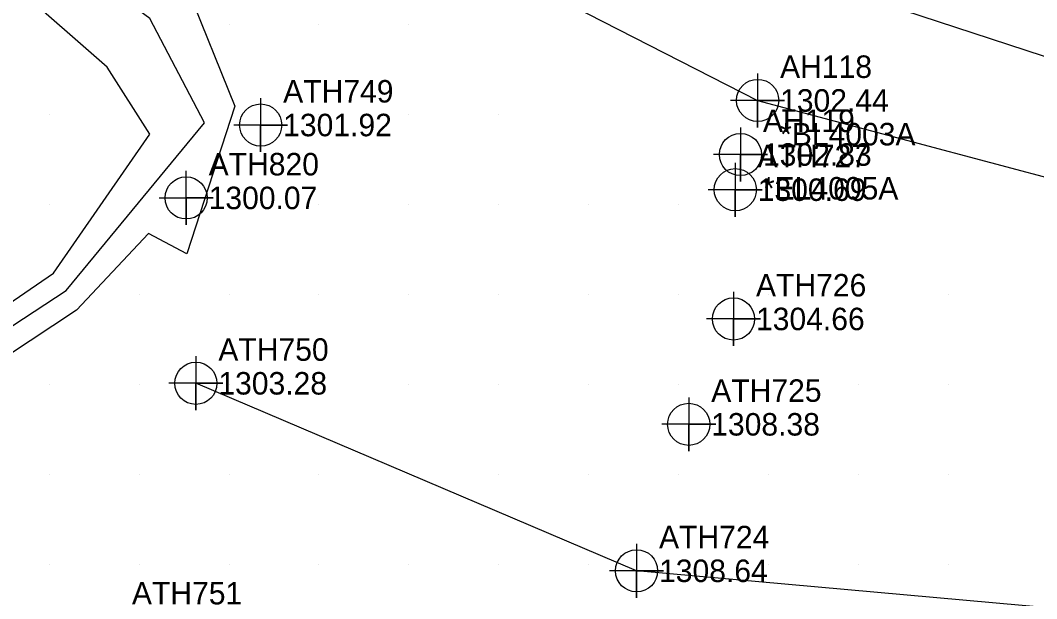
# Model space of a CAD drawing. Extents: x 1234484 to 1235382, y 695050 to 695510.
# Drawn here: x 1234936.8 to 1235049.8, y 695206.2 to 695270.5 of the extents above; entities that cross this region are included whole.
import ezdxf

# ---------------------------------------------------------------- set-up
doc = ezdxf.new("R2010")
doc.units = 0
for name, color, linetype in [('Exist DTM Breakline', 7, 'Continuous'), ('Exist DTM Breakline Cogo Comment', 7, 'Continuous'), ('Exist DTM Breakline Cogo Elevation', 7, 'Continuous'), ('Exist DTM Breakline Cogo Number', 7, 'Continuous'), ('Exist DTM Breakline Cogo Point CELL', 7, 'Continuous'), ('Exist DTM Breakline Underwater', 7, 'Continuous'), ('Exist DTM Crownline', 7, 'Continuous'), ('Exist DTM Drainline Cogo Comment', 7, 'Continuous'), ('Exist DTM Drainline Cogo Elevation', 7, 'Continuous'), ('Exist DTM Drainline Cogo Number', 7, 'Continuous'), ('Exist DTM Drainline Cogo Point CELL', 7, 'Continuous'), ('Exist DTM QL2 LIDAR Elevation Point', 7, 'Continuous'), ('Exist DTM Regular Point CELL', 7, 'Continuous'), ('Exist DTM Regular Point Cogo Elevation', 7, 'Continuous'), ('Exist DTM Regular Point Cogo Number', 7, 'Continuous'), ('Exist DTM Regular Point Underwater CELL', 7, 'Continuous'), ('Exist DTM Regular Point Underwater Cogo Elevation', 7, 'Continuous'), ('Exist DTM Regular Point Underwater Cogo Number', 7, 'Continuous'), ('Exist Hydro Stream or Body of Water', 7, 'Continuous'), ('Exist Hydro Stream or Body of Water Cogo Elevation', 7, 'Continuous'), ('Exist Hydro Stream or Body of Water Cogo Number', 7, 'Continuous'), ('Exist Hydro Stream or Body of Water Cogo Point CELL', 7, 'Continuous'), ('Exist Roads EOP', 7, 'Continuous')]:
    doc.layers.add(name, color=color, linetype=linetype)

msp = doc.modelspace()

# ---------------------------------------------------------------- linework, layer by layer
at = {"layer": 'Exist DTM Breakline'}
for points in [[(1234933.683, 695295.436), (1234929.419, 695292.356), (1234942.895, 695281.98), (1234955.338, 695274.07), (1234960.662, 695260.925), (1234955.311, 695244.507), (1234951.042, 695246.761), (1234943.062, 695238.239), (1234919.786, 695222.886), (1234917.573, 695214.076), (1234899.933, 695199.243), (1234885.657, 695179.089)], [(1234882.128, 695182.331), (1234896.107, 695201.799), (1234912.336, 695216.249), (1234916.953, 695226.235), (1234940.483, 695242.348), (1234951.207, 695257.798), (1234946.446, 695265.278), (1234936.421, 695274.091), (1234919.314, 695287.826), (1234914.388, 695289.733)], [(1235242.403, 695122.486), (1235188.913, 695150.987), (1235163.662, 695164.651), (1235112.238, 695183.191), (1235055.183, 695204.784), (1235005.3, 695209.27), (1234956.312, 695230.116)]]:
    msp.add_lwpolyline(points, dxfattribs=at)
at = {"layer": 'Exist DTM Breakline Cogo Point CELL'}
for points in [[(1235016.848, 695258.551), (1235016.848, 695252.551), (1235016.848, 695255.551), (1235019.848, 695255.551), (1235013.848, 695255.551)], [(1234956.312, 695233.116), (1234956.312, 695227.116), (1234956.312, 695230.116), (1234959.312, 695230.116), (1234953.312, 695230.116)], [(1235005.3, 695212.27), (1235005.3, 695206.27), (1235005.3, 695209.27), (1235008.3, 695209.27), (1235002.3, 695209.27)]]:
    msp.add_lwpolyline(points, dxfattribs=at)
for centre in [(1235016.848, 695255.551), (1234956.312, 695230.116), (1235005.3, 695209.27)]:
    msp.add_circle(centre, 2.344, dxfattribs=at)
at = {"layer": 'Exist DTM Breakline Underwater'}
msp.add_lwpolyline([(1234948.239, 695292.841), (1234952.805, 695292.84), (1234960.83, 695292.864), (1234972.599, 695288.481), (1235023.203, 695275.502), (1235056.399, 695264.585), (1235086.587, 695258.395), (1235121.582, 695234.941), (1235168.445, 695213.485), (1235191.313, 695204.186), (1235209.05, 695188.429), (1235246.922, 695166.749), (1235265.478, 695149.496)], dxfattribs=at)
at = {"layer": 'Exist DTM Crownline'}
msp.add_spline([(1234978.534, 695313.159), (1235028.867, 695302.317), (1235079.475, 695286.154), (1235130.202, 695265.942), (1235178.94, 695242.599), (1235226.8, 695217.474)], degree=3, dxfattribs=at)
at = {"layer": 'Exist DTM Drainline Cogo Point CELL'}
msp.add_lwpolyline([(1235018.754, 695264.568), (1235018.754, 695258.568), (1235018.754, 695261.568), (1235021.754, 695261.568), (1235015.754, 695261.568)], dxfattribs=at)
msp.add_circle((1235018.754, 695261.568), 2.344, dxfattribs=at)
at = {"layer": 'Exist DTM QL2 LIDAR Elevation Point'}
for p, q in [((1234960, 695270), (1234960, 695270)), ((1234970, 695270), (1234970, 695270)), ((1234980, 695270), (1234980, 695270)), ((1234940, 695260), (1234940, 695260)), ((1234970, 695260), (1234970, 695260)), ((1234980, 695260), (1234980, 695260)), ((1234990, 695260), (1234990, 695260)), ((1234940, 695250), (1234940, 695250)), ((1234960, 695250), (1234960, 695250)), ((1234970, 695250), (1234970, 695250)), ((1234980, 695250), (1234980, 695250)), ((1234990, 695250), (1234990, 695250)), ((1235000, 695250), (1235000, 695250)), ((1235010, 695250), (1235010, 695250)), ((1234950, 695240), (1234950, 695240)), ((1234960, 695240), (1234960, 695240)), ((1234970, 695240), (1234970, 695240)), ((1234980, 695240), (1234980, 695240)), ((1234990, 695240), (1234990, 695240)), ((1235000, 695240), (1235000, 695240)), ((1235010, 695240), (1235010, 695240)), ((1235020, 695240), (1235020, 695240)), ((1235030, 695240), (1235030, 695240)), ((1235040, 695240), (1235040, 695240)), ((1234940, 695230), (1234940, 695230)), ((1234950, 695230), (1234950, 695230)), ((1234960, 695230), (1234960, 695230)), ((1234970, 695230), (1234970, 695230)), ((1234980, 695230), (1234980, 695230)), ((1234990, 695230), (1234990, 695230)), ((1235000, 695230), (1235000, 695230)), ((1235010, 695230), (1235010, 695230)), ((1235020, 695230), (1235020, 695230)), ((1235030, 695230), (1235030, 695230)), ((1235040, 695230), (1235040, 695230)), ((1234940, 695220), (1234940, 695220)), ((1234950, 695220), (1234950, 695220)), ((1234960, 695220), (1234960, 695220)), ((1234970, 695220), (1234970, 695220)), ((1234990, 695220), (1234990, 695220)), ((1235000, 695220), (1235000, 695220)), ((1235010, 695220), (1235010, 695220)), ((1235020, 695220), (1235020, 695220)), ((1235030, 695220), (1235030, 695220)), ((1235040, 695220), (1235040, 695220)), ((1234940, 695210), (1234940, 695210)), ((1234950, 695210), (1234950, 695210)), ((1234960, 695210), (1234960, 695210)), ((1234970, 695210), (1234970, 695210)), ((1234980, 695210), (1234980, 695210)), ((1234990, 695210), (1234990, 695210)), ((1235000, 695210), (1235000, 695210)), ((1235010, 695210), (1235010, 695210)), ((1235020, 695210), (1235020, 695210)), ((1235030, 695210), (1235030, 695210)), ((1235040, 695210), (1235040, 695210))]:
    msp.add_line(p, q, dxfattribs=at)
at = {"layer": 'Exist DTM Regular Point CELL'}
for points in [[(1234963.516, 695261.834), (1234963.516, 695255.834), (1234963.516, 695258.834), (1234966.516, 695258.834), (1234960.516, 695258.834)], [(1235016.075, 695240.272), (1235016.075, 695234.272), (1235016.075, 695237.272), (1235019.075, 695237.272), (1235013.075, 695237.272)], [(1235011.1, 695228.556), (1235011.1, 695222.556), (1235011.1, 695225.556), (1235014.1, 695225.556), (1235008.1, 695225.556)]]:
    msp.add_lwpolyline(points, dxfattribs=at)
for centre in [(1234963.516, 695258.834), (1235016.075, 695237.272), (1235011.1, 695225.556)]:
    msp.add_circle(centre, 2.344, dxfattribs=at)
at = {"layer": 'Exist DTM Regular Point Underwater CELL'}
msp.add_lwpolyline([(1235016.271, 695254.643), (1235016.271, 695248.643), (1235016.271, 695251.643), (1235019.271, 695251.643), (1235013.271, 695251.643)], dxfattribs=at)
msp.add_circle((1235016.271, 695251.643), 2.344, dxfattribs=at)
at = {"layer": 'Exist Hydro Stream or Body of Water'}
for points in [[(1234884.024, 695180.655), (1234897.944, 695200.742), (1234915.887, 695215.628), (1234918.027, 695224.801), (1234941.893, 695240.452), (1234957.27, 695259.086), (1234951.207, 695270.685), (1234942.31, 695277.234), (1234922.587, 695292.008)], [(1234944.112, 695289.587), (1234953.373, 695288.163), (1234962.335, 695289.234), (1234972.332, 695285.316), (1235018.754, 695261.568)], [(1235018.754, 695261.568), (1235053.271, 695252.381), (1235081.661, 695240.144), (1235119.353, 695226.521), (1235169.371, 695199.43), (1235188.125, 695189.805), (1235205.75, 695183.352), (1235242.093, 695153.734), (1235263.468, 695141.323)]]:
    msp.add_lwpolyline(points, dxfattribs=at)
at = {"layer": 'Exist Hydro Stream or Body of Water Cogo Point CELL'}
msp.add_lwpolyline([(1234952.232, 695250.729), (1234958.232, 695250.729), (1234955.232, 695250.729), (1234955.232, 695247.729), (1234955.232, 695253.729)], dxfattribs=at)
msp.add_circle((1234955.232, 695250.729), 2.344, dxfattribs=at)
at = {"layer": 'Exist Roads EOP'}
for points in [[(1234989.744, 695321.275), (1235032.632, 695310.758), (1235082.97, 695294.625), (1235134.247, 695274.482), (1235183.928, 695250.955), (1235232.115, 695225.68)], [(1234969.592, 695304.589), (1235025.451, 695292.964), (1235076.313, 695277.193), (1235126.218, 695256.569), (1235174.523, 695234.324), (1235222.247, 695208.988)]]:
    msp.add_spline(points, degree=3, dxfattribs=at)

# ---------------------------------------------------------------- texts
at = {"layer": 'Exist DTM Breakline Cogo Comment'}
msp.add_text('*EL4005A', height=2.5, dxfattribs=at).set_placement((1235019.348, 695250.551))
at = {"layer": 'Exist DTM Breakline Cogo Elevation'}
for s, p in [('1302.83', (1235019.348, 695254.301)), ('1303.28', (1234958.812, 695228.866)), ('1308.64', (1235007.8, 695208.02))]:
    msp.add_text(s, height=2.5, dxfattribs=at).set_placement(p)
at = {"layer": 'Exist DTM Breakline Cogo Number'}
for s, p in [('AH119', (1235019.348, 695258.051)), ('ATH750', (1234958.812, 695232.616)), ('ATH724', (1235007.8, 695211.77))]:
    msp.add_text(s, height=2.5, dxfattribs=at).set_placement(p)
at = {"layer": 'Exist DTM Drainline Cogo Comment'}
msp.add_text('*BL4003A', height=2.5, dxfattribs=at).set_placement((1235021.254, 695256.568))
at = {"layer": 'Exist DTM Drainline Cogo Elevation'}
msp.add_text('1302.44', height=2.5, dxfattribs=at).set_placement((1235021.254, 695260.318))
at = {"layer": 'Exist DTM Drainline Cogo Number'}
msp.add_text('AH118', height=2.5, dxfattribs=at).set_placement((1235021.254, 695264.068))
at = {"layer": 'Exist DTM Regular Point Cogo Elevation'}
for s, p in [('1301.92', (1234966.016, 695257.584)), ('1304.66', (1235018.575, 695236.022)), ('1308.38', (1235013.6, 695224.306))]:
    msp.add_text(s, height=2.5, dxfattribs=at).set_placement(p)
at = {"layer": 'Exist DTM Regular Point Cogo Number'}
for s, p in [('ATH749', (1234966.016, 695261.334)), ('ATH726', (1235018.575, 695239.772)), ('ATH725', (1235013.6, 695228.056)), ('ATH751', (1234949.204, 695205.535))]:
    msp.add_text(s, height=2.5, dxfattribs=at).set_placement(p)
at = {"layer": 'Exist DTM Regular Point Underwater Cogo Elevation'}
msp.add_text('1300.69', height=2.5, dxfattribs=at).set_placement((1235018.771, 695250.393))
at = {"layer": 'Exist DTM Regular Point Underwater Cogo Number'}
msp.add_text('ATH727', height=2.5, dxfattribs=at).set_placement((1235018.771, 695254.143))
at = {"layer": 'Exist Hydro Stream or Body of Water Cogo Elevation'}
msp.add_text('1300.07', height=2.5, dxfattribs=at).set_placement((1234957.732, 695249.479))
at = {"layer": 'Exist Hydro Stream or Body of Water Cogo Number'}
msp.add_text('ATH820', height=2.5, dxfattribs=at).set_placement((1234957.732, 695253.229))

doc.saveas('drawing.dxf')
